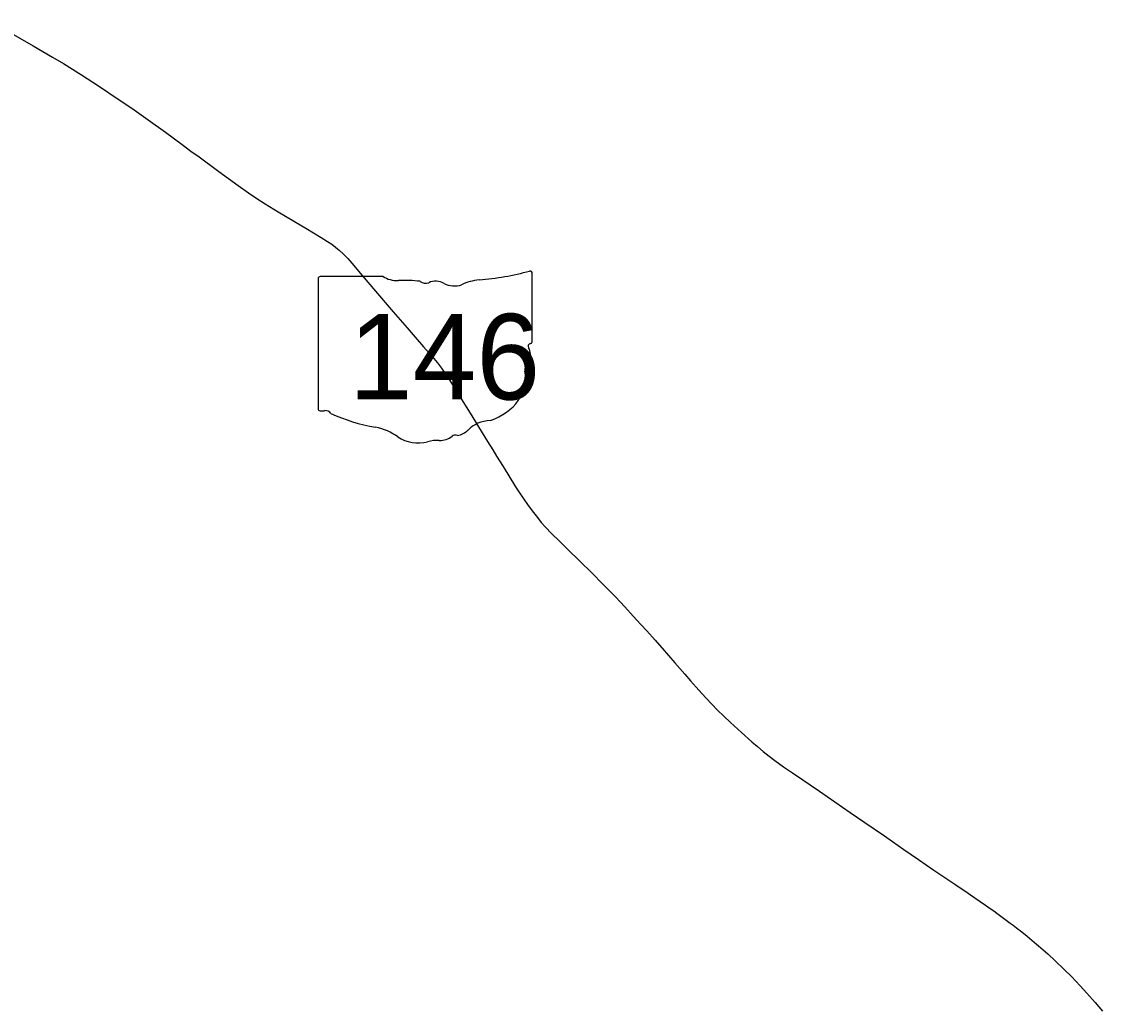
# Model space of a CAD drawing. Extents: x 2015843 to 2287843, y 623733 to 799733.
# Drawn here: x 2083047 to 2097188, y 732143 to 745032 of the extents above; entities that cross this region are included whole.
import ezdxf

# ---------------------------------------------------------------- set-up
doc = ezdxf.new("R2010")
doc.units = 0
doc.layers.add('GM_X_State_Route', color=7, linetype='Continuous')
doc.layers.add('GM_X_State_Shield', color=7, linetype='Continuous')

msp = doc.modelspace()

# ---------------------------------------------------------------- linework, layer by layer
at = {"layer": 'GM_X_State_Route'}
msp.add_line((2095590, 733514), (2095658, 733466), dxfattribs=at)
for points in [[(2082641, 745032), (2083197, 744714), (2083453, 744566), (2083594, 744482), (2083830, 744334), (2084065, 744183), (2084325, 744010), (2084487, 743899), (2084702, 743747), (2084928, 743584), (2085147, 743423), (2085280, 743325), (2085351, 743273), (2085629, 743069), (2085881, 742886), (2086015, 742791), (2086124, 742718), (2086234, 742647), (2086402, 742544), (2086713, 742361), (2086767, 742329)], [(2086767, 742329), (2086966, 742208), (2087051, 742156), (2087104, 742118), (2087155, 742080), (2087181, 742058), (2087204, 742039), (2087253, 741994), (2087314, 741930), (2087367, 741869), (2087505, 741707), (2087676, 741506), (2087910, 741233), (2088091, 741022), (2088197, 740900), (2088306, 740776), (2088414, 740652), (2088487, 740566), (2088539, 740497), (2088586, 740430), (2088649, 740334), (2088798, 740096), (2088936, 739872), (2089074, 739650), (2089144, 739537), (2089211, 739427), (2089262, 739343), (2089347, 739207), (2089510, 738945), (2089562, 738864), (2089609, 738794), (2089676, 738700), (2089744, 738608), (2089795, 738542), (2089846, 738478), (2089900, 738415), (2089978, 738333), (2090085, 738230), (2090166, 738151), (2090377, 737945), (2090482, 737842), (2090680, 737645), (2090817, 737504), (2090940, 737372), (2091050, 737251), (2091151, 737143), (2091228, 737057), (2091337, 736935), (2091423, 736837), (2091426, 736833), (2091595, 736639), (2091659, 736564), (2091724, 736490), (2091799, 736403), (2091909, 736282), (2091999, 736183), (2092077, 736100), (2092154, 736019), (2092235, 735940), (2092322, 735858), (2092464, 735729), (2092600, 735607), (2092675, 735543), (2092749, 735479), (2092826, 735418), (2092904, 735359), (2093014, 735280), (2093132, 735198), (2093269, 735106), (2093364, 735042), (2093485, 734958), (2093889, 734679), (2094080, 734550), (2094336, 734375), (2094444, 734300), (2094592, 734196), (2094781, 734065), (2094984, 733926), (2095256, 733743), (2095432, 733623), (2095462, 733602), (2095590, 733514)], [(2095658, 733466), (2095689, 733445), (2095783, 733380), (2095788, 733376), (2095981, 733234), (2096021, 733204), (2096086, 733155), (2096112, 733135), (2096202, 733063), (2096327, 732958), (2096350, 732937), (2096475, 732829), (2096572, 732740), (2096690, 732626), (2096783, 732533), (2096896, 732414), (2096985, 732317), (2097093, 732194), (2097188, 732081)]]:
    msp.add_lwpolyline(points, dxfattribs=at)
at = {"layer": 'GM_X_State_Shield'}
for p, q in [((2089729, 740849), (2089729, 741738)), ((2086928, 741667), (2086928, 739966)), ((2087776, 741696), (2086955, 741696)), ((2089729, 740849), (2089729, 740849))]:
    msp.add_line(p, q, dxfattribs=at)
for centre, major_axis, start_param, end_param in [((2088731, 744016), (2971, 0), 4.814394, 5.042369), ((2089698, 741742), (31.2, 0), 6.141152, 7.989035), ((2086960, 741671), (32.5, 0), 1.712693, 3.28349), ((2087971, 741894), (315, 0), 4.042523, 4.731795), ((2088075, 740741), (1130, 0), 1.404758, 1.657858), ((2088332, 741679), (90.8, 0), 3.836095, 5.185415), ((2088465, 741483), (189, 0), 0.950623, 2.079405), ((2088709, 741753), (227, 0), 4.081561, 5.145723), ((2089110, 741177), (598, 0), 1.699011, 2.107814), ((2089722, 740783), (48.3, 0), 1.883978, 3.671073), ((2089415, 740671), (290, 0), 5.934695, 6.695948), ((2089696, 740845), (33.4, 0), 5.05454, 6.418171), ((2089841, 740476), (211, 0), 2.387724, 3.262537), ((2088898, 740363), (743, 0), 5.101752, 6.440018), ((2086960, 739962), (32.7, 0), 3.00124, 4.508301), ((2086965, 740136), (250, 0), 4.665946, 4.897461), ((2087016, 739868), (90.1, 0), 0.519207, 1.627899), ((2088154, 741396), (2146, 0), 4.195997, 4.488961), ((2087514, 739202), (671, 0), 0.823519, 1.323587), ((2089211, 739488), (407, 0), 1.647645, 2.488434), ((2088240, 739859), (426, 0), 4.026481, 4.996735), ((2088517, 739732), (227, 0), 4.691044, 5.507374), ((2088723, 739567), (63.9, 0), 1.147584, 2.315152), ((2088695, 739801), (240, 0), 4.937069, 5.64225), ((2088486, 739271), (350, 0), 1.495662, 1.94098)]:
    msp.add_ellipse(centre, major_axis=major_axis, ratio=0.8, start_param=start_param, end_param=end_param, dxfattribs=at)

# ---------------------------------------------------------------- texts
msp.add_text('146', height=1120.7, dxfattribs=at).set_placement((2087331, 740086))

doc.saveas('drawing.dxf')
